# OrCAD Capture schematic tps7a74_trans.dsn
size A
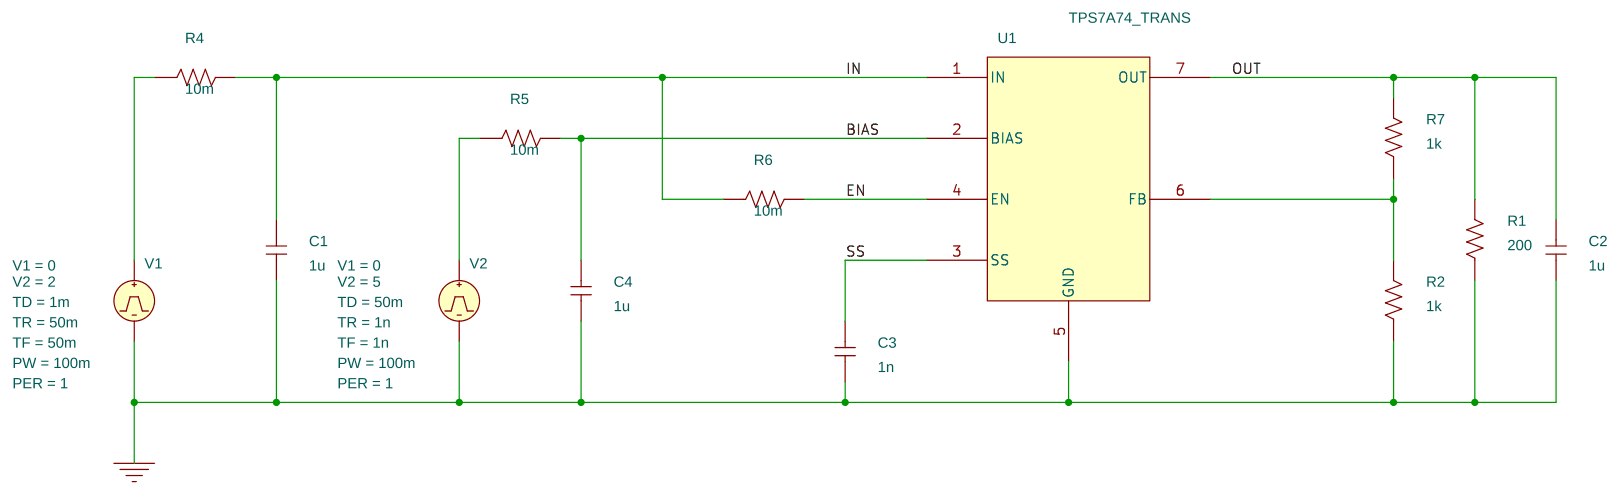
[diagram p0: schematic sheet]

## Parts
C1  1u  [RAD/CK05]
C2  1u  [RAD/CK05]
C3  1n  [RAD/CK05]
C4  1u  [RAD/CK05]
R1  200  [AX/RC05]
R2  1k  [AX/RC05]
R4  10m  [AX/RC05]
R5  10m  [AX/RC05]
R6  10m  [AX/RC05]
R7  1k  [AX/RC05]
U1  TPS7A74_TRANS
V1  VPULSE
V2  VPULSE

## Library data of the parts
C1-C4 = C
R1 R2 R4-R7 = R
U1 = TPS7A74_TRANS_2
V1 = VPULSE: PER: 1; PW: 100m; TD: 1m; TF: 50m; TR: 50m; V1: 0; V2: 2
V2 = VPULSE: PER: 1; PW: 100m; TD: 50m; TF: 1n; TR: 1n; V1: 0; V2: 5

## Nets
0: C1.1 C2.1 C3.1 C4.1 R1.1 R2.1 U1.5(GND) V1.2(-) V2.2(-)
BIAS: C4.2 R5.2 U1.2(BIAS)
EN: R6.2 U1.4(EN)
IN: C1.2 R4.2 R6.1 U1.1(IN)
OUT: C2.2 R1.2 R7.2 U1.7(OUT)
SS: C3.2 U1.3(SS)
N242481: R4.1 V1.1(+)
N242587: R5.1 V2.1(+)
N242633: R2.2 R7.1 U1.6(FB)
